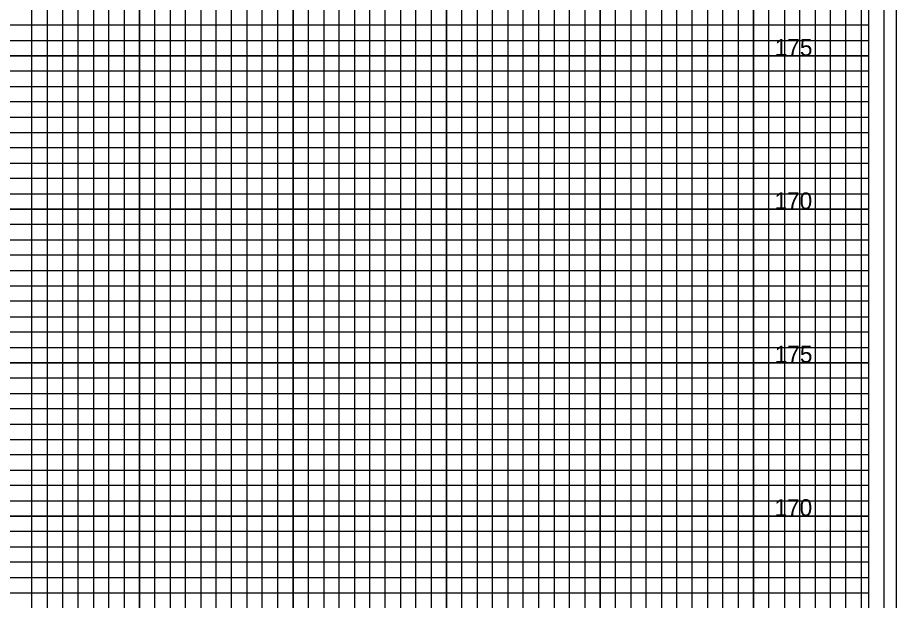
# Model space of a CAD drawing. Extents: x -4 to 103, y -2 to 209.
# Drawn here: x 74.78 to 103.4, y 32.25 to 51.25 of the extents above; entities that cross this region are included whole.
import ezdxf

# ---------------------------------------------------------------- set-up
doc = ezdxf.new("R2010")
doc.units = 0
for name, color, linetype in [('Prop XS Elevation Labels', 7, 'Continuous'), ('Sheet Cross Section CELL', 7, 'Continuous'), ('Sheet Cross Section Grid Major CELL', 7, 'Continuous'), ('Sheet Cross Section Grid Middle CELL', 7, 'Continuous'), ('Sheet DOT Grid CELL', 7, 'Continuous'), ('Sheet Plot Border Inside CELL', 7, 'Continuous'), ('Sheet Plot Border Outside CELL', 7, 'Continuous')]:
    doc.layers.add(name, color=color, linetype=linetype)

msp = doc.modelspace()

# ---------------------------------------------------------------- linework, layer by layer
at = {"layer": 'Sheet Cross Section CELL'}
msp.add_lwpolyline([(102.5, 65), (0, 65), (0, 0), (102.5, 0)], close=True, dxfattribs=at)
at = {"layer": 'Sheet Cross Section Grid Major CELL'}
for points in [[(91.25, 0), (91.25, 63.425), (93.75, 63.425), (93.75, 0)], [(96.25, 0), (96.25, 63.425), (98.75, 63.425), (98.75, 0)], [(101.25, 0), (101.25, 63.425)], [(76.25, 0), (76.25, 62), (78.75, 62), (78.75, 0)], [(81.25, 0), (81.25, 62), (83.75, 62), (83.75, 0)], [(86.25, 0), (86.25, 62), (88.75, 62), (88.75, 0)], [(0, 47.5), (102.5, 47.5), (102.5, 50), (0, 50)], [(0, 42.5), (102.5, 42.5), (102.5, 45), (0, 45)], [(0, 37.5), (102.5, 37.5), (102.5, 40), (0, 40)], [(0, 32.5), (102.5, 32.5), (102.5, 35), (0, 35)]]:
    msp.add_lwpolyline(points, dxfattribs=at)
at = {"layer": 'Sheet Cross Section Grid Middle CELL'}
for points in [[(90.25, 0), (90.25, 63.425), (90.75, 63.425), (90.75, 0)], [(91.75, 0), (91.75, 63.425), (92.25, 63.425), (92.25, 0)], [(92.75, 0), (92.75, 63.425), (93.25, 63.425), (93.25, 0)], [(94.25, 0), (94.25, 63.425), (94.75, 63.425), (94.75, 0)], [(95.25, 0), (95.25, 63.425), (95.75, 63.425), (95.75, 0)], [(96.75, 0), (96.75, 63.425), (97.25, 63.425), (97.25, 0)], [(97.75, 0), (97.75, 63.425), (98.25, 63.425), (98.25, 0)], [(99.25, 0), (99.25, 63.425), (99.75, 63.425), (99.75, 0)], [(100.25, 0), (100.25, 63.425)], [(100.25, 63.425), (100.75, 63.425), (100.75, 0), (101.75, 0), (101.75, 63.425), (102.25, 63.425), (102.25, 0)], [(75.25, 0), (75.25, 62), (75.75, 62), (75.75, 0)], [(76.75, 0), (76.75, 62), (77.25, 62), (77.25, 0)], [(77.75, 0), (77.75, 62), (78.25, 62), (78.25, 0)], [(79.25, 0), (79.25, 62), (79.75, 62), (79.75, 0)], [(80.25, 0), (80.25, 62), (80.75, 62), (80.75, 0)], [(81.75, 0), (81.75, 62), (82.25, 62), (82.25, 0)], [(82.75, 0), (82.75, 62), (83.25, 62), (83.25, 0)], [(84.25, 0), (84.25, 62), (84.75, 62), (84.75, 0)], [(85.25, 0), (85.25, 62), (85.75, 62), (85.75, 0)], [(86.75, 0), (86.75, 62), (87.25, 62), (87.25, 0)], [(87.75, 0), (87.75, 62), (88.25, 62), (88.25, 0)], [(89.25, 0), (89.25, 62), (89.75, 62), (89.75, 0)], [(0, 50.5), (102.5, 50.5), (102.5, 51), (0, 51)], [(0, 49), (102.5, 49), (102.5, 49.5), (0, 49.5)], [(0, 48), (102.5, 48), (102.5, 48.5), (0, 48.5)], [(0, 46.5), (102.5, 46.5), (102.5, 47), (0, 47)], [(0, 45.5), (102.5, 45.5), (102.5, 46), (0, 46)], [(0, 44), (102.5, 44), (102.5, 44.5), (0, 44.5)], [(0, 43), (102.5, 43), (102.5, 43.5), (0, 43.5)], [(0, 41.5), (102.5, 41.5), (102.5, 42), (0, 42)], [(0, 40.5), (102.5, 40.5), (102.5, 41), (0, 41)], [(0, 39), (102.5, 39), (102.5, 39.5), (0, 39.5)], [(0, 38), (102.5, 38), (102.5, 38.5), (0, 38.5)], [(0, 36.5), (102.5, 36.5), (102.5, 37), (0, 37)], [(0, 35.5), (102.5, 35.5), (102.5, 36), (0, 36)], [(0, 34), (102.5, 34), (102.5, 34.5), (0, 34.5)], [(0, 33), (102.5, 33), (102.5, 33.5), (0, 33.5)]]:
    msp.add_lwpolyline(points, dxfattribs=at)
at = {"layer": 'Sheet DOT Grid CELL'}
for p, q in [((91.25, 0), (91.25, 63.425)), ((93.75, 0), (93.75, 63.425)), ((96.25, 0), (96.25, 63.425)), ((98.75, 0), (98.75, 63.425)), ((101.25, 0), (101.25, 63.425)), ((76.25, 0), (76.25, 62)), ((78.75, 0), (78.75, 62)), ((81.25, 0), (81.25, 62)), ((83.75, 0), (83.75, 62)), ((86.25, 0), (86.25, 62)), ((88.75, 0), (88.75, 62)), ((0, 50), (102.5, 50)), ((0, 47.5), (102.5, 47.5)), ((0, 45), (102.5, 45)), ((0, 42.5), (102.5, 42.5)), ((0, 40), (102.5, 40)), ((0, 37.5), (102.5, 37.5)), ((0, 35), (102.5, 35)), ((0, 32.5), (102.5, 32.5))]:
    msp.add_line(p, q, dxfattribs=at)
at = {"layer": 'Sheet Plot Border Inside CELL'}
msp.add_lwpolyline([(103, 66), (-2.8, 66), (-2.8, -1), (103, -1)], close=True, dxfattribs=at)
at = {"layer": 'Sheet Plot Border Outside CELL'}
msp.add_lwpolyline([(103.4, 67.4), (-3.5, 67.4), (-3.5, -2.425), (103.4, -2.425)], close=True, dxfattribs=at)

# ---------------------------------------------------------------- texts
at = {"layer": 'Prop XS Elevation Labels'}
for s, p in [('175', (99.43825, 50)), ('170', (99.42958, 45)), ('175', (99.43825, 40)), ('170', (99.42958, 35))]:
    msp.add_text(s, height=0.55, dxfattribs=at).set_placement(p)

doc.saveas('drawing.dxf')
